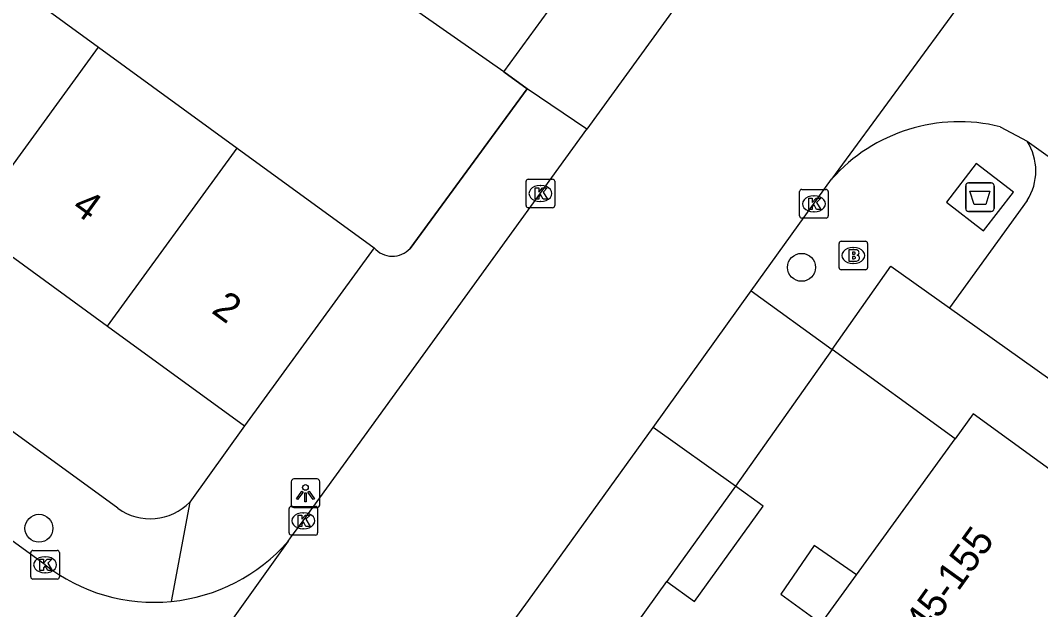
# Model space of a CAD drawing. Extents: x 159675 to 160530, y 382179 to 382901.
# Drawn here: x 160206.75 to 160242.45, y 382500.55 to 382521.17 of the extents above; entities that cross this region are included whole.
import ezdxf

# ---------------------------------------------------------------- set-up
doc = ezdxf.new("R2010")
doc.units = 0
for name, color, linetype in [('IMGEO_Afval_apart_plaats', 7, 'Continuous'), ('IMGEO_Boom', 7, 'Continuous'), ('IMGEO_Brandkraan', 7, 'Continuous'), ('IMGEO_Kolk', 7, 'Continuous'), ('IMGEO_Lichtpunt', 7, 'Continuous'), ('IMGEO_Muur', 7, 'Continuous'), ('IMGEO_Pand', 7, 'Continuous'), ('IMGEO_Pand_nummerreeks', 7, 'Continuous'), ('IMGEO_Parkeervlak_open', 7, 'Continuous'), ('IMGEO_Rijbaan_lokaal_gesloten', 7, 'Continuous'), ('IMGEO_Rijbaan_lokaal_open', 7, 'Continuous'), ('IMGEO_Voetpad_gesloten', 7, 'Continuous'), ('IMGEO_Voetpad_open', 7, 'Continuous')]:
    doc.layers.add(name, color=color, linetype=linetype)

msp = doc.modelspace()

# ---------------------------------------------------------------- linework, layer by layer
at = {"layer": 'IMGEO_Afval_apart_plaats'}
for p, q in [((160239.835, 382514.584), (160239.835, 382515.384)), ((160239.835, 382515.384), (160239.835, 382514.584)), ((160239.935, 382515.484), (160240.725, 382515.484)), ((160240.725, 382515.484), (160239.935, 382515.484)), ((160240.825, 382515.384), (160240.825, 382514.584)), ((160240.825, 382514.584), (160240.825, 382515.384)), ((160240.725, 382514.484), (160239.935, 382514.484)), ((160239.935, 382514.484), (160240.725, 382514.484))]:
    msp.add_line(p, q, dxfattribs=at)
msp.add_lwpolyline([(160239.978, 382515.198), (160240.682, 382515.198), (160240.533, 382514.728), (160240.127, 382514.728), (160239.978, 382515.198)], dxfattribs=at)
for centre, start, end in [((160239.935, 382515.384), 90, 180), ((160239.935, 382515.384), 90, 180), ((160240.725, 382515.384), 0, 90), ((160240.725, 382515.384), 360, 90), ((160239.935, 382514.584), 180, 270), ((160239.935, 382514.584), 180, 270), ((160240.725, 382514.584), 270, 0), ((160240.725, 382514.584), 270, 0)]:
    msp.add_arc(centre, 0.1, start, end, dxfattribs=at)
at = {"layer": 'IMGEO_Boom'}
for centre in [(160234.088, 382512.527), (160207.401, 382503.395)]:
    msp.add_circle(centre, 0.489, dxfattribs=at)
at = {"layer": 'IMGEO_Brandkraan'}
for p, q in [((160235.4, 382512.515), (160235.4, 382513.367)), ((160235.475, 382513.441), (160236.327, 382513.441)), ((160235.888, 382513.221), (160235.913, 382513.221)), ((160236.401, 382513.367), (160236.401, 382512.515)), ((160235.911, 382512.661), (160235.886, 382512.661)), ((160236.327, 382512.441), (160235.475, 382512.441))]:
    msp.add_line(p, q, dxfattribs=at)
for points in [[(160235.4, 382512.515), (160235.4, 382513.367)], [(160235.475, 382513.441), (160236.327, 382513.441)], [(160236.401, 382513.367), (160236.401, 382512.515)], [(160235.748, 382513.141), (160235.748, 382512.741), (160235.961, 382512.741)], [(160235.979, 382513.141), (160235.748, 382513.141)], [(160235.927, 382513.06), (160235.873, 382513.06), (160235.873, 382512.984)], [(160235.873, 382512.984), (160235.926, 382512.984)], [(160235.935, 382512.908), (160235.873, 382512.908), (160235.873, 382512.827)], [(160235.873, 382512.827), (160235.935, 382512.827)], [(160236.327, 382512.441), (160235.475, 382512.441)]]:
    msp.add_lwpolyline(points, dxfattribs=at)
for centre, radius, start, end in [((160235.477, 382513.365), 0.0765, 91.552, 178.448), ((160235.477, 382513.365), 0.0765, 91.552, 178.448), ((160236.325, 382513.365), 0.0765, 1.552, 88.448), ((160236.325, 382513.365), 0.0765, 1.552, 88.448), ((160235.928, 382513.022), 0.0379, 267.8285, 90.9355), ((160235.936, 382512.867), 0.0404, 269.8759, 90.5077), ((160235.983, 382512.996), 0.145, 59.4692, 91.5367), ((160236.008, 382513.043), 0.0922, 285.5137, 58.1501), ((160236.013, 382512.851), 0.105, 301.3115, 78.989), ((160235.477, 382512.517), 0.0765, 181.552, 268.448), ((160235.477, 382512.517), 0.0765, 181.552, 268.448), ((160235.967, 382512.992), 0.251, 268.6676, 293.5347), ((160236.325, 382512.517), 0.0765, 271.552, 358.448), ((160236.325, 382512.517), 0.0765, 271.552, 358.448)]:
    msp.add_arc(centre, radius, start, end, dxfattribs=at)
for centre, major_axis, ratio, start_param, end_param in [((160235.887, 382512.941), (-0.387, 0.002), 0.722429, 4.712389, 7.853982), ((160235.912, 382512.941), (-0.39, 0.002), 0.717154, 1.570796, 4.712389)]:
    msp.add_ellipse(centre, major_axis=major_axis, ratio=ratio, start_param=start_param, end_param=end_param, dxfattribs=at)
at = {"layer": 'IMGEO_Kolk'}
for p, q in [((160224.45, 382514.687), (160224.45, 382515.539)), ((160224.525, 382515.613), (160225.377, 382515.613)), ((160224.938, 382515.393), (160224.963, 382515.393)), ((160225.451, 382515.539), (160225.451, 382514.687)), ((160234.022, 382514.326), (160234.022, 382515.178)), ((160234.097, 382515.252), (160234.949, 382515.252)), ((160234.51, 382515.032), (160234.535, 382515.032)), ((160235.023, 382515.178), (160235.023, 382514.326)), ((160225.377, 382514.613), (160224.525, 382514.613)), ((160224.961, 382514.833), (160224.936, 382514.833)), ((160234.949, 382514.252), (160234.097, 382514.252)), ((160234.533, 382514.472), (160234.508, 382514.472)), ((160216.153, 382503.233), (160216.153, 382504.085)), ((160216.228, 382504.159), (160217.08, 382504.159)), ((160216.641, 382503.939), (160216.666, 382503.939)), ((160217.154, 382504.085), (160217.154, 382503.233)), ((160216.664, 382503.379), (160216.639, 382503.379)), ((160217.08, 382503.159), (160216.228, 382503.159)), ((160207.116, 382501.693), (160207.116, 382502.545)), ((160207.191, 382502.619), (160208.043, 382502.619)), ((160208.117, 382502.545), (160208.117, 382501.693)), ((160207.604, 382502.399), (160207.629, 382502.399)), ((160207.627, 382501.839), (160207.602, 382501.839)), ((160208.043, 382501.619), (160207.191, 382501.619))]:
    msp.add_line(p, q, dxfattribs=at)
for points in [[(160224.45, 382514.687), (160224.45, 382515.539)], [(160224.525, 382515.613), (160225.377, 382515.613)], [(160224.771, 382515.313), (160224.894, 382515.313), (160224.894, 382515.162), (160225.024, 382515.313), (160225.188, 382515.313), (160225.042, 382515.162), (160225.195, 382514.913), (160225.043, 382514.913), (160224.958, 382515.077), (160224.894, 382515.01), (160224.894, 382514.913), (160224.771, 382514.913), (160224.771, 382515.313)], [(160225.451, 382515.539), (160225.451, 382514.687)], [(160234.022, 382514.326), (160234.022, 382515.178)], [(160234.097, 382515.252), (160234.949, 382515.252)], [(160235.023, 382515.178), (160235.023, 382514.326)], [(160225.377, 382514.613), (160224.525, 382514.613)], [(160234.343, 382514.952), (160234.466, 382514.952), (160234.466, 382514.801), (160234.596, 382514.952), (160234.76, 382514.952), (160234.614, 382514.801), (160234.767, 382514.552), (160234.615, 382514.552), (160234.53, 382514.716), (160234.466, 382514.649), (160234.466, 382514.552), (160234.343, 382514.552), (160234.343, 382514.952)], [(160234.949, 382514.252), (160234.097, 382514.252)], [(160216.153, 382503.233), (160216.153, 382504.085)], [(160216.228, 382504.159), (160217.08, 382504.159)], [(160217.154, 382504.085), (160217.154, 382503.233)], [(160216.474, 382503.859), (160216.597, 382503.859), (160216.597, 382503.708), (160216.727, 382503.859), (160216.891, 382503.859), (160216.745, 382503.708), (160216.898, 382503.459), (160216.746, 382503.459), (160216.661, 382503.623), (160216.597, 382503.556), (160216.597, 382503.459), (160216.474, 382503.459), (160216.474, 382503.859)], [(160217.08, 382503.159), (160216.228, 382503.159)], [(160207.116, 382501.693), (160207.116, 382502.545)], [(160207.191, 382502.619), (160208.043, 382502.619)], [(160208.117, 382502.545), (160208.117, 382501.693)], [(160207.437, 382502.319), (160207.56, 382502.319), (160207.56, 382502.168), (160207.69, 382502.319), (160207.854, 382502.319), (160207.708, 382502.168), (160207.861, 382501.919), (160207.709, 382501.919), (160207.624, 382502.083), (160207.56, 382502.016), (160207.56, 382501.919), (160207.437, 382501.919), (160207.437, 382502.319)], [(160208.043, 382501.619), (160207.191, 382501.619)]]:
    msp.add_lwpolyline(points, dxfattribs=at)
for centre, start, end in [((160224.527, 382515.537), 91.552, 178.448), ((160224.527, 382515.537), 91.552, 178.448), ((160225.375, 382515.537), 1.552, 88.448), ((160225.375, 382515.537), 1.552, 88.448), ((160234.099, 382515.176), 91.552, 178.448), ((160234.099, 382515.176), 91.552, 178.448), ((160234.947, 382515.176), 1.552, 88.448), ((160234.947, 382515.176), 1.552, 88.448), ((160224.527, 382514.689), 181.552, 268.448), ((160224.527, 382514.689), 181.552, 268.448), ((160225.375, 382514.689), 271.552, 358.448), ((160225.375, 382514.689), 271.552, 358.448), ((160234.099, 382514.328), 181.552, 268.448), ((160234.099, 382514.328), 181.552, 268.448), ((160234.947, 382514.328), 271.552, 358.448), ((160234.947, 382514.328), 271.552, 358.448), ((160216.23, 382504.083), 91.552, 178.448), ((160216.23, 382504.083), 91.552, 178.448), ((160217.078, 382504.083), 1.552, 88.448), ((160217.078, 382504.083), 1.552, 88.448), ((160216.23, 382503.235), 181.552, 268.448), ((160216.23, 382503.235), 181.552, 268.448), ((160217.078, 382503.235), 271.552, 358.448), ((160217.078, 382503.235), 271.552, 358.448), ((160207.193, 382502.543), 91.552, 178.448), ((160207.193, 382502.543), 91.552, 178.448), ((160208.041, 382502.543), 1.552, 88.448), ((160208.041, 382502.543), 1.552, 88.448), ((160207.193, 382501.695), 181.552, 268.448), ((160207.193, 382501.695), 181.552, 268.448), ((160208.041, 382501.695), 271.552, 358.448), ((160208.041, 382501.695), 271.552, 358.448)]:
    msp.add_arc(centre, 0.0765, start, end, dxfattribs=at)
for centre, major_axis, ratio, start_param, end_param in [((160224.937, 382515.113), (-0.387, 0.002), 0.722429, 4.712389, 7.853982), ((160224.962, 382515.113), (-0.39, 0.002), 0.717154, 1.570796, 4.712389), ((160234.509, 382514.752), (-0.387, 0.002), 0.722429, 4.712389, 7.853982), ((160234.534, 382514.752), (-0.39, 0.002), 0.717154, 1.570796, 4.712389), ((160216.64, 382503.659), (-0.387, 0.002), 0.722429, 4.712389, 7.853982), ((160216.665, 382503.659), (-0.39, 0.002), 0.717154, 1.570796, 4.712389), ((160207.603, 382502.119), (-0.387, 0.002), 0.722429, 4.712389, 7.853982), ((160207.628, 382502.119), (-0.39, 0.002), 0.717154, 1.570796, 4.712389)]:
    msp.add_ellipse(centre, major_axis=major_axis, ratio=ratio, start_param=start_param, end_param=end_param, dxfattribs=at)
at = {"layer": 'IMGEO_Lichtpunt'}
for p, q in [((160216.23, 382505.025), (160216.23, 382504.218)), ((160216.23, 382505.025), (160216.23, 382504.218)), ((160217.132, 382505.12), (160216.324, 382505.12)), ((160217.132, 382505.12), (160216.324, 382505.12)), ((160217.226, 382504.218), (160217.226, 382505.025)), ((160217.226, 382504.218), (160217.226, 382505.025)), ((160216.324, 382504.124), (160217.132, 382504.124)), ((160216.324, 382504.124), (160217.132, 382504.124))]:
    msp.add_line(p, q, dxfattribs=at)
for points in [[(160216.604, 382504.689), (160216.643, 382504.661), (160216.455, 382504.399), (160216.417, 382504.426), (160216.604, 382504.689)], [(160216.706, 382504.641), (160216.753, 382504.641), (160216.753, 382504.319), (160216.706, 382504.319), (160216.706, 382504.641)], [(160216.816, 382504.661), (160216.854, 382504.688), (160217.041, 382504.426), (160217.002, 382504.398), (160216.816, 382504.661)]]:
    msp.add_lwpolyline(points, dxfattribs=at)
msp.add_circle((160216.729, 382504.823), 0.0994, dxfattribs=at)
for centre, start, end in [((160216.324, 382505.025), 90, 180), ((160216.324, 382505.025), 90, 180), ((160217.132, 382505.025), 0, 90), ((160217.132, 382505.025), 0, 90), ((160216.324, 382504.218), 180, 270), ((160216.324, 382504.218), 180, 270), ((160217.132, 382504.218), 270, 0), ((160217.132, 382504.218), 270, 360)]:
    msp.add_arc(centre, 0.0946, start, end, dxfattribs=at)
at = {"layer": 'IMGEO_Muur'}
for points in [[(160223.667, 382519.369), (160224.489, 382518.771)], [(160224.489, 382518.771), (160220.389, 382513.187)]]:
    msp.add_lwpolyline(points, dxfattribs=at)
msp.add_arc((160219.771, 382513.759), 0.842, 220.4041, 317.2297, dxfattribs=at)
at = {"layer": 'IMGEO_Pand'}
for points in [[(160223.667, 382519.369), (160220.311, 382521.713), (160218.523, 382522.962), (160221.031, 382526.41)], [(160204.67, 382523.742), (160209.487, 382520.234)], [(160223.667, 382519.369), (160226.104, 382522.72)], [(160204.949, 382513.998), (160209.487, 382520.234)], [(160209.487, 382520.234), (160214.339, 382516.701)], [(160209.802, 382510.465), (160214.339, 382516.701)], [(160214.339, 382516.701), (160219.13, 382513.213)], [(160204.949, 382513.998), (160209.802, 382510.465)], [(160219.13, 382513.213), (160214.591, 382506.978)], [(160209.802, 382510.465), (160214.591, 382506.978)], [(160238.256, 382487.19), (160247.547, 382500), (160248.493, 382501.304), (160240.092, 382507.396), (160239.464, 382506.53)], [(160236.011, 382501.771), (160239.464, 382506.53)], [(160234.771, 382500.06), (160236.011, 382501.771)]]:
    msp.add_lwpolyline(points, dxfattribs=at)
at = {"layer": 'IMGEO_Parkeervlak_open'}
msp.add_lwpolyline([(160239.266, 382511.108), (160254.885, 382500), (160257.309, 382498.276), (160259.072, 382500), (160260.575, 382501.47)], dxfattribs=at)
at = {"layer": 'IMGEO_Rijbaan_lokaal_gesloten'}
for points in [[(160244.516, 382528.409), (160235.142, 382515.615)], [(160232.376, 382525.365), (160226.58, 382517.362)], [(160216.121, 382502.946), (160216.208, 382503.063), (160216.652, 382503.655), (160218.061, 382505.6), (160226.58, 382517.362)], [(160232.328, 382511.703), (160235.142, 382515.615)], [(160228.891, 382506.926), (160232.328, 382511.703)], [(160216.503, 382489.659), (160218.852, 382492.909), (160223.908, 382500), (160224.532, 382500.867), (160228.891, 382506.926)], [(160216.121, 382502.946), (160214.024, 382500), (160205.773, 382488.409)]]:
    msp.add_lwpolyline(points, dxfattribs=at)
at = {"layer": 'IMGEO_Rijbaan_lokaal_open'}
for points in [[(160207.614, 382502.119), (160170.916, 382528.842)], [(160241.036, 382517.45), (160241.981, 382516.945)], [(160241.981, 382516.945), (160263.203, 382501.762)]]:
    msp.add_lwpolyline(points, dxfattribs=at)
for centre, radius, start, end in [((160239.605, 382511.664), 5.96, 76.1053, 138.4809), ((160211.432, 382507.009), 6.204, 275.5563, 319.0885), ((160211.434, 382507.014), 6.209, 232.0345, 275.5378)]:
    msp.add_arc(centre, radius, start, end, dxfattribs=at)
at = {"layer": 'IMGEO_Voetpad_gesloten'}
msp.add_lwpolyline([(160241.501, 382515.153), (160240.201, 382516.16), (160239.158, 382514.814), (160240.458, 382513.807), (160241.501, 382515.153)], dxfattribs=at)
at = {"layer": 'IMGEO_Voetpad_open'}
for points in [[(160210.164, 382504.096), (160187.205, 382520.79)], [(160224.489, 382518.771), (160223.667, 382519.369)], [(160220.389, 382513.187), (160224.489, 382518.771)], [(160226.58, 382517.362), (160224.489, 382518.771)], [(160241.986, 382514.861), (160239.266, 382511.108)], [(160235.158, 382509.653), (160237.217, 382512.565), (160239.266, 382511.108)], [(160232.328, 382511.703), (160235.158, 382509.653)], [(160235.158, 382509.653), (160231.777, 382504.869)], [(160239.464, 382506.53), (160235.158, 382509.653)], [(160214.591, 382506.978), (160212.685, 382504.314)], [(160231.777, 382504.869), (160228.891, 382506.926)], [(160231.777, 382504.869), (160229.377, 382501.534)], [(160229.377, 382501.534), (160230.345, 382500.837), (160232.745, 382504.172), (160231.777, 382504.869)], [(160212.685, 382504.314), (160212.033, 382500.834)], [(160236.011, 382501.771), (160234.535, 382502.788), (160233.361, 382501.083), (160234.771, 382500.06)], [(160227.898, 382499.479), (160228.273, 382500), (160229.377, 382501.534)]]:
    msp.add_lwpolyline(points, dxfattribs=at)
for centre, radius, start, end in [((160240.347, 382515.899), 1.94, 327.6592, 32.6157), ((160219.771, 382513.759), 0.842, 220.4041, 317.2297), ((160211.299, 382505.656), 1.929, 233.9663, 315.9182)]:
    msp.add_arc(centre, radius, start, end, dxfattribs=at)

# ---------------------------------------------------------------- texts
at = {"layer": 'IMGEO_Pand_nummerreeks'}
for s, rotation, p in [('4', 323.9419, (160208.507, 382514.524)), ('2', 323.9419, (160213.402, 382510.961)), ('145-155', 54.3622, (160238.01, 382498.986))]:
    msp.add_text(s, height=1, rotation=rotation, dxfattribs=at).set_placement(p)

doc.saveas('drawing.dxf')
